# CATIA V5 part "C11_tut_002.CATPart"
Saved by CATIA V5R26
Part number: Part2
Bounding box of the stored display mesh (mm): x 0 to 175, y -36.636 to 105, z 0 to 36.66
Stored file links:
  D:\_Deepak\CATIA\CATIA V5-6R2016_Deepak\Resources\Tutorial Files\Tutorials\c11_catia_v5_6r2016_tut\C11_tut_002.CATPart
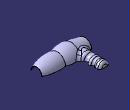
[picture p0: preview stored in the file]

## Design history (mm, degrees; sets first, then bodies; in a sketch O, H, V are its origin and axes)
Body1 (main body)
  Plane1: type Offset, RefPlane yz-plane, Offset 50
  Set1
    Plane2: type Offset, RefPlane yz-plane, Offset 100 {= Plane1.Offset+`Plane2.Relative Offset`}
    Plane3: type Offset, RefPlane yz-plane, Offset 175
  Sketch1 on yz-plane, origin (0, 0, 0), H (0, 1, 0), V (0, 0, 1)
    arc A1 centre (0, 0) radius 25 from (25, 0) to (-25, 0) ccw
    point P1 (-25, 0)
    radius A1 = 25
  Sketch2 on Plane1, origin (50, 0, 0), H (0, 1, 0), V (0, 0, 1)
    arc A1 centre (0, 0) radius 35 from (35, 0) to (-35, 0) ccw
    point P1 (-35, 0)
    radius A1 = 35
  Sketch3 on Plane2, origin (100, 0, 0), H (0, 1, 0), V (0, 0, 1)
    arc A1 centre (0, 0) radius 30 from (30, 0) to (-30, 0) ccw
    point P1 (-30, 0)
    radius A1 = 30
  Sketch4 on Plane3, origin (175, 0, 0), H (0, 1, 0), V (0, 0, 1)
    arc A1 centre (0, 0) radius 20 from (20, 0) to (-20, 0) ccw
    point P1 (-20, 0)
    radius A1 = 20
  Sketch5 on xy-plane, origin (0, 0, 0), H (1, 0, 0), V (0, 1, 0)
    point P1 (0, -25)
    line L1 (0, -25) -> (50, -35)
    point P2 (50, -35)
    reference projected point E1 (50, -35) from Sketch2.P1
    reference projected point E2 (0, -25) from Sketch1.P1
    arc A1 centre (66.816, 49.3399) radius 86 from (50, -35) to (100, -30) ccw
    point P4 (100, -30)
    reference projected point E3 (100, -30) from Sketch3.P1
    arc A2 centre (121.7543, 93.0924) radius 125 from (100, -30) to (175, -20) ccw
    point P6 (175, -20)
    reference projected point E4 (175, -20) from Sketch4.P1
    radius A1 = 86
    radius A2 = 125
    coincidence: P1 V, P2 E1, P1 E2, P4 E3, E4 P6
  Sketch6 on xy-plane, origin (0, 0, 0), H (1, 0, 0), V (0, 1, 0)
    arc A1 centre (121.7543, -93.0924) radius 125 from (100, 30) to (175, 20) cw
    arc A2 centre (66.816, -49.3399) radius 86 from (50, 35) to (100, 30) cw
    line L1 (0, 25) -> (50, 35)
    fix: A1, L1, A2
  Loft1: Sections (Sketch1; Sketch2; Sketch3; Sketch4), Guides (Sketch5; Sketch6)
  Sketch7 on xy-plane, origin (0, 0, 0), H (1, 0, 0), V (0, 1, 0)
    point P1 (15, 105)
    line L1 (15, 105) -> (15, 0)
    point P2 (15, 0)
    point P3 (15, 105)
    distance H P1 = 105
    distance V L1 = 15
    coincidence: P2 H, P3 P1
    vertical: L1 V
  Plane4: type Normal, Curve Sketch7, RefPoint Sketch7.P3, Ratio 0
  Sketch8 on Plane4, origin (0, 105, 0), H (1, 0, 0), V (0, 0, 1)
    arc A1 centre (32.5, 0) radius 17.5 from (15, 0) to (50, 0) cw
    point P1 (32.5, 0)
    point P2 (15, 0)
    point P3 (50, 0)
    reference projected line E1 (0, 0) -> (-50, 0) from edge of Loft1
    reference projected point E2 (15, 0) from Sketch7.P2
    radius A1 = 17.5
    coincidence: P2 H, P3 H, P1 E1, E2 P2
  Sketch9 on xy-plane, origin (0, 0, 0), H (1, 0, 0), V (0, 1, 0)
    line L1 (50, 105) -> (51.989, 90.8478)
    point P1 (50, 105)
    arc A1 centre (45.0571, 89.8736) radius 7 from (51.989, 90.8478) to (49.6106, 84.5571) cw
    arc A2 centre (53.5135, 80) radius 6 from (49.6106, 84.5571) to (51.6373, 74.3009) ccw
    point P5 (53.5135, 80)
    point P6 (51.6373, 74.3009)
    arc A3 centre (50.1519, 69.7891) radius 4.75 from (51.6373, 74.3009) to (52.3972, 65.6033) cw
    point P8 (51.6373, 74.3009)
    arc A4 centre (56.6515, 57.6723) radius 9 from (52.3972, 65.6033) to (52.5866, 49.6425) ccw
    point P10 (56.6515, 57.6723)
    arc A5 centre (47.1667, 38.9362) radius 12 from (52.5866, 49.6425) to (59.0499, 40.6063) cw
    axis line L2 (50, 105) -> (61.1145, 25.9165)
    line L3 (59.0499, 40.6063) -> (62.3136, 17.3845)
    reference projected point E1 (50, 105) from Sketch8.P3
    reference projected line E2 (50, 105) -> (15, 105) from Sketch8.A1
    radius A1 = 7
    radius A2 = 6
    radius A3 = 4.75
    radius A4 = 9
    radius A5 = 12
    distance P5 P1 V = 25
    angle L1 E2 = 98
    tangency: A2 A1, A3 L2, A3 A2, A3 A4, A5 A4, A5 L2, L3 A5, L3 L2, A1 L1
    coincidence: P8 A2, L2 L1, P5 L2, P8 P6, P10 L2, P1 E1
  Loft2: Sections Sketch8, Guides (Sketch9; Sketch7)
  Trim1: Trimmed (Loft1; Loft2)
  Line1: type PtPt, FirstPoint vertex [face of Loft1], SecondPoint vertex [face of Loft1]
  Line2: type PtPt, FirstPoint vertex [face of Loft2], SecondPoint vertex [face of Loft2]
  Line3: type PtPt, FirstPoint vertex [face of Loft1], SecondPoint vertex [face of Loft1]
  Fill1: Boundary (Line3; edge of Loft1)
  Fill2: Boundary (edge of Loft1; Line1)
  Fill3: Boundary (edge of Loft2; Line2)
  Join1: Elements (Fill2; Fill3; Fill1; Trim1)
  CloseSurface1: CloseElement Join1
  Fillet1: radius 12, on edge [face of CloseSurface1 | face of CloseSurface1]
  Fillet2: radius 8, on edge [face of CloseSurface1 | face of CloseSurface1]
  Shell1: ExtOffset 0, Face (face of CloseSurface1; face of CloseSurface1; face of CloseSurface1), IntOffset 1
